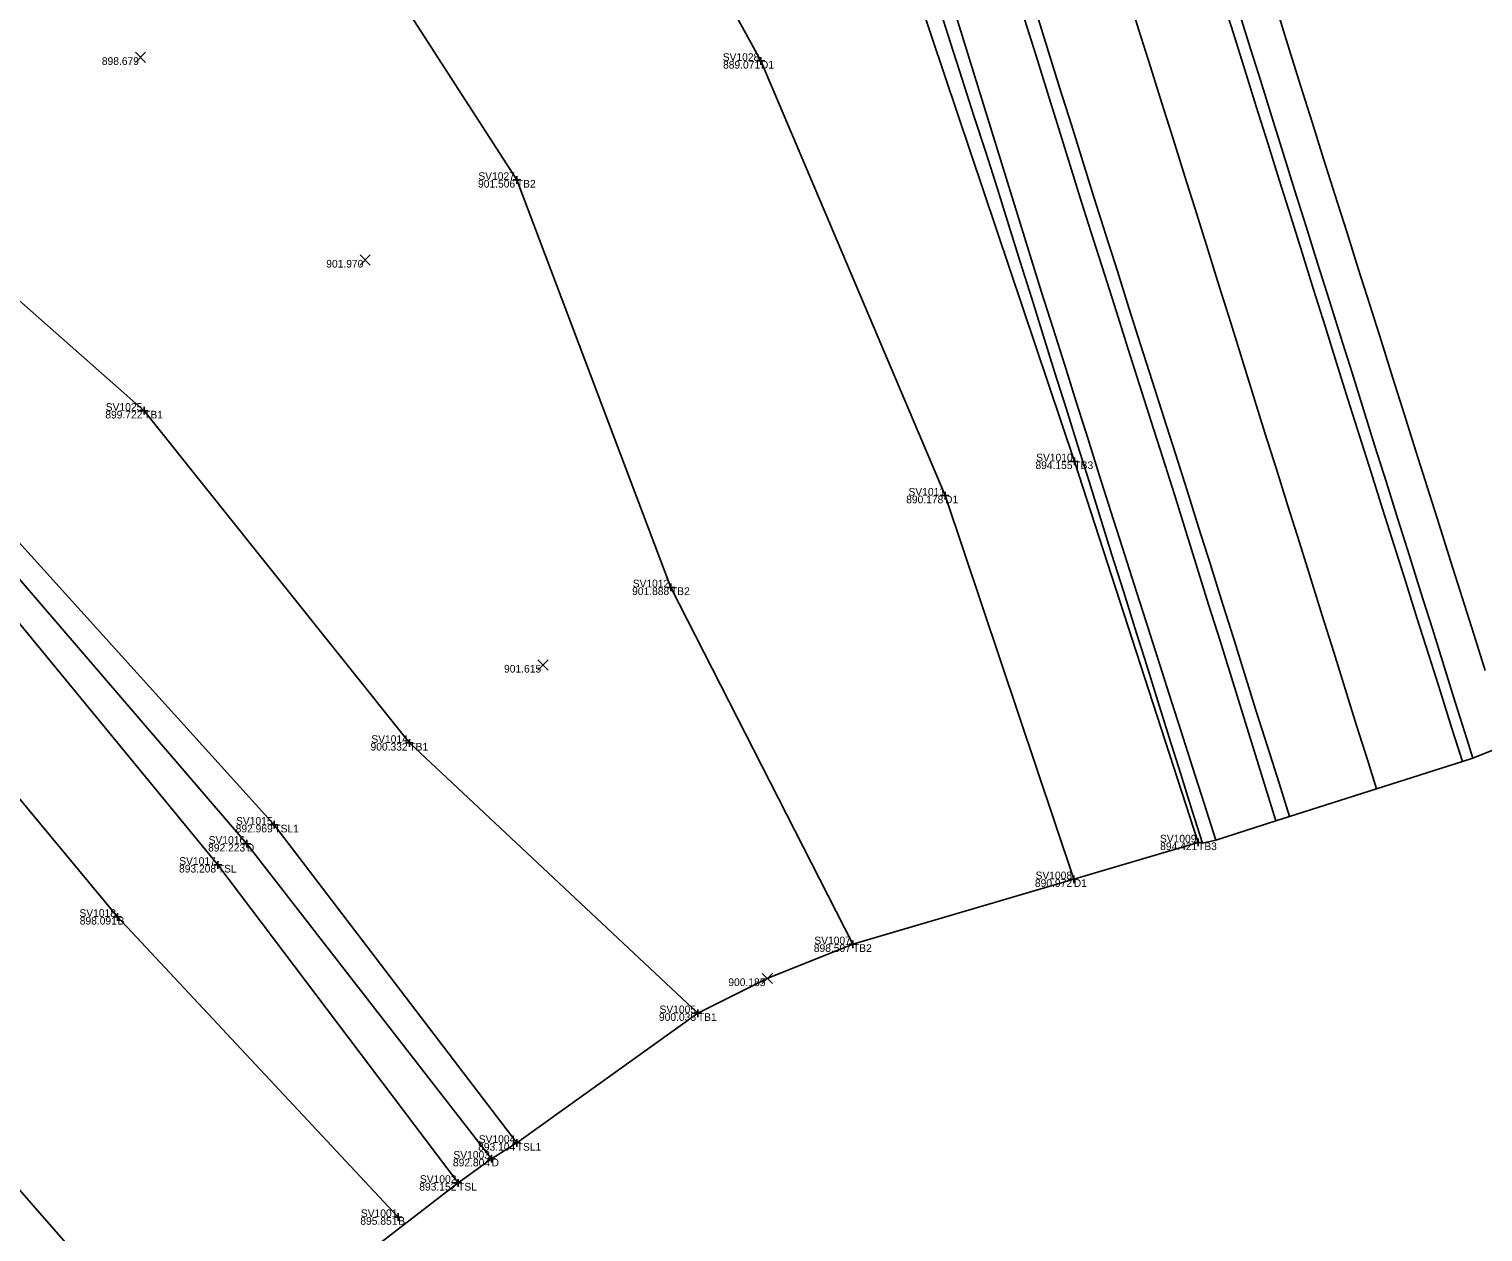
# Model space of a CAD drawing. Extents: x 1918148 to 1919797, y 624701 to 627089.
# Drawn here: x 1919158.7 to 1919348.2, y 625398.1 to 625555 of the extents above; entities that cross this region are included whole.
import ezdxf

# ---------------------------------------------------------------- set-up
doc = ezdxf.new("R2010")
doc.units = 0
for name, color, linetype in [('DR_X_Ditch', 7, 'Continuous'), ('DT_X_Terrain_Boundary', 7, 'Continuous'), ('PM_X_Edge_Line', 7, 'Continuous'), ('PM_X_Lane_Line', 7, 'Continuous'), ('PV_X_EOP', 7, 'Continuous'), ('PV_X_Shoulder_Aggregate', 7, 'Continuous'), ('PV_X_Shoulder_Rumble_Strip', 7, 'Continuous'), ('SV_X_Break_Lines', 7, 'Continuous'), ('SV_X_Random_Point', 7, 'Continuous'), ('SV_X_Shot_Marker', 7, 'Continuous'), ('SV_X_Text_Comment', 7, 'Continuous'), ('SV_X_Text_Elevation', 7, 'Continuous'), ('SV_X_Text_Name', 7, 'Continuous'), ('SV_X_Toe_of_Slope', 7, 'Continuous'), ('SV_X_Top_of_Bank', 7, 'Continuous')]:
    doc.layers.add(name, color=color, linetype=linetype)

msp = doc.modelspace()

# ---------------------------------------------------------------- linework, layer by layer
at = {"layer": 'DR_X_Ditch'}
for points in [[(1919294.9, 625444.11), (1919278.12, 625494.14), (1919254.13, 625550.83), (1919231.31, 625592.46), (1919223.61, 625606.59), (1919220.8, 625619.65), (1919215.15, 625628.65)], [(1919219.02, 625407.66), (1919187.13, 625448.73), (1919151.86, 625489.75), (1919129.02, 625518.23), (1919101.03, 625555.91), (1919077.07, 625591.12), (1919056.34, 625619.29)]]:
    msp.add_lwpolyline(points, dxfattribs=at)
at = {"layer": 'DT_X_Terrain_Boundary'}
for points in [[(1919348.54, 625471.32), (1919347.03, 625476.08), (1919345.53, 625480.85), (1919344.02, 625485.62), (1919342.52, 625490.39), (1919341.01, 625495.16), (1919339.5, 625499.92), (1919338, 625504.69), (1919336.49, 625509.46), (1919334.99, 625514.23), (1919333.49, 625519), (1919331.98, 625523.77), (1919330.48, 625528.53), (1919328.97, 625533.3), (1919327.47, 625538.07), (1919325.97, 625542.84), (1919324.47, 625547.61), (1919322.98, 625552.38), (1919321.48, 625557.15)], [(1919180.03, 625377.77), (1919214.66, 625404.51), (1919219.02, 625407.66), (1919222.3, 625409.72), (1919245.91, 625426.64), (1919254.95, 625431.18), (1919266.12, 625435.63), (1919294.9, 625444.11), (1919311.1, 625448.91), (1919311.66, 625448.82), (1919313.4, 625449.21), (1919321.24, 625451.71), (1919323.02, 625452.28), (1919334.37, 625455.9), (1919345.55, 625459.47), (1919346.92, 625459.9), (1919351.55, 625461.78)]]:
    msp.add_lwpolyline(points, dxfattribs=at)
at = {"layer": 'PM_X_Edge_Line'}
for points in [[(1919314.22, 625559.2), (1919315.71, 625554.42), (1919317.2, 625549.65), (1919318.69, 625544.88), (1919320.18, 625540.1), (1919321.67, 625535.33), (1919323.17, 625530.56), (1919324.66, 625525.79), (1919326.16, 625521.02), (1919327.65, 625516.25), (1919329.15, 625511.47), (1919330.64, 625506.7), (1919332.14, 625501.93), (1919333.64, 625497.16), (1919335.15, 625492.4), (1919336.65, 625487.63), (1919338.16, 625482.86), (1919339.67, 625478.09), (1919341.17, 625473.33), (1919342.68, 625468.56), (1919344.19, 625463.79), (1919345.55, 625459.47)], [(1919290.11, 625556.8), (1919291.6, 625552.02), (1919293.09, 625547.25), (1919294.59, 625542.48), (1919296.08, 625537.71), (1919297.57, 625532.93), (1919299.07, 625528.16), (1919300.58, 625523.4), (1919302.09, 625518.63), (1919303.61, 625513.87), (1919305.12, 625509.1), (1919306.63, 625504.34), (1919308.14, 625499.57), (1919309.66, 625494.8), (1919311.16, 625490.04), (1919312.66, 625485.27), (1919314.16, 625480.5), (1919315.66, 625475.73), (1919317.15, 625470.96), (1919318.65, 625466.18), (1919320.15, 625461.41), (1919321.65, 625456.64), (1919323.02, 625452.28)]]:
    msp.add_lwpolyline(points, dxfattribs=at)
at = {"layer": 'PM_X_Lane_Line'}
msp.add_lwpolyline([(1919301.89, 625559.61), (1919303.39, 625554.84), (1919304.88, 625550.07), (1919306.38, 625545.3), (1919307.88, 625540.53), (1919309.38, 625535.76), (1919310.88, 625530.99), (1919312.37, 625526.22), (1919313.86, 625521.44), (1919315.35, 625516.67), (1919316.84, 625511.9), (1919318.33, 625507.13), (1919319.82, 625502.35), (1919321.31, 625497.58), (1919322.81, 625492.81), (1919324.3, 625488.04), (1919325.8, 625483.27), (1919327.29, 625478.5), (1919328.78, 625473.72), (1919330.28, 625468.95), (1919331.77, 625464.18), (1919333.27, 625459.41), (1919334.37, 625455.9)], dxfattribs=at)
at = {"layer": 'PV_X_EOP'}
for points in [[(1919313.4, 625449.21), (1919311.88, 625453.97), (1919310.36, 625458.74), (1919308.84, 625463.5), (1919307.32, 625468.26), (1919305.8, 625473.03), (1919304.28, 625477.79), (1919302.76, 625482.55), (1919301.24, 625487.32), (1919299.73, 625492.08), (1919298.23, 625496.85), (1919296.73, 625501.62), (1919295.22, 625506.39), (1919293.72, 625511.16), (1919292.22, 625515.93), (1919290.71, 625520.69), (1919289.21, 625525.46), (1919287.73, 625530.24), (1919286.26, 625535.02), (1919284.78, 625539.8), (1919283.31, 625544.57), (1919281.84, 625549.35), (1919280.37, 625554.13), (1919278.9, 625558.91)], [(1919321.48, 625557.15), (1919322.98, 625552.38), (1919324.47, 625547.61), (1919325.97, 625542.84), (1919327.47, 625538.07), (1919328.97, 625533.3), (1919330.48, 625528.53), (1919331.98, 625523.77), (1919333.49, 625519), (1919334.99, 625514.23), (1919336.49, 625509.46), (1919338, 625504.69), (1919339.5, 625499.92), (1919341.01, 625495.16), (1919342.52, 625490.39), (1919344.02, 625485.62), (1919345.53, 625480.85), (1919347.03, 625476.08), (1919348.54, 625471.32)]]:
    msp.add_lwpolyline(points, dxfattribs=at)
at = {"layer": 'PV_X_Shoulder_Aggregate'}
msp.add_lwpolyline([(1919277.3, 625557.96), (1919278.83, 625553.2), (1919280.36, 625548.44), (1919281.89, 625543.68), (1919283.42, 625538.92), (1919284.94, 625534.15), (1919286.44, 625529.38), (1919287.93, 625524.61), (1919289.43, 625519.84), (1919290.92, 625515.07), (1919292.41, 625510.3), (1919293.91, 625505.53), (1919295.4, 625500.75), (1919296.9, 625495.98), (1919298.39, 625491.21), (1919299.88, 625486.44), (1919301.38, 625481.67), (1919302.87, 625476.9), (1919304.37, 625472.12), (1919305.86, 625467.35), (1919307.35, 625462.58), (1919308.85, 625457.81), (1919310.34, 625453.04), (1919311.66, 625448.82)], dxfattribs=at)
at = {"layer": 'PV_X_Shoulder_Rumble_Strip'}
for points in [[(1919316.25, 625557.87), (1919317.73, 625553.1), (1919319.22, 625548.32), (1919320.71, 625543.55), (1919322.2, 625538.78), (1919323.69, 625534.01), (1919325.19, 625529.24), (1919326.68, 625524.46), (1919328.18, 625519.69), (1919329.67, 625514.92), (1919331.17, 625510.15), (1919332.66, 625505.38), (1919334.16, 625500.61), (1919335.65, 625495.84), (1919337.15, 625491.07), (1919338.65, 625486.29), (1919340.14, 625481.52), (1919341.64, 625476.75), (1919343.13, 625471.98), (1919344.63, 625467.21), (1919346.12, 625462.44), (1919346.92, 625459.9)], [(1919288.49, 625556.28), (1919289.98, 625551.51), (1919291.47, 625546.73), (1919292.95, 625541.96), (1919294.44, 625537.19), (1919295.93, 625532.41), (1919297.43, 625527.64), (1919298.94, 625522.88), (1919300.45, 625518.11), (1919301.96, 625513.35), (1919303.47, 625508.58), (1919304.99, 625503.81), (1919306.5, 625499.05), (1919308.01, 625494.28), (1919309.51, 625489.51), (1919311, 625484.74), (1919312.48, 625479.96), (1919313.96, 625475.19), (1919315.44, 625470.41), (1919316.92, 625465.64), (1919318.41, 625460.86), (1919319.89, 625456.09), (1919321.24, 625451.71)]]:
    msp.add_lwpolyline(points, dxfattribs=at)
at = {"layer": 'SV_X_Break_Lines'}
msp.add_lwpolyline([(1919206.86, 625400.05), (1919170.29, 625439.2), (1919138.05, 625478.01), (1919112.93, 625508.78), (1919087.56, 625546), (1919063.33, 625584.96), (1919048.27, 625604.54), (1919031.79, 625617.49), (1919020.42, 625620.88), (1919013.82, 625627.54), (1919010.2, 625639.42), (1919006.75, 625653.62), (1919000.26, 625672.97)], dxfattribs=at)
at = {"layer": 'SV_X_Random_Point'}
for p, q in [((1919172.6, 625550.64), (1919173.93, 625551.97)), ((1919172.6, 625551.97), (1919173.93, 625550.64)), ((1919201.88, 625524.21), (1919203.21, 625525.55)), ((1919201.88, 625525.55), (1919203.21, 625524.21)), ((1919225.06, 625471.39), (1919226.39, 625472.73)), ((1919225.06, 625472.73), (1919226.39, 625471.39)), ((1919254.29, 625430.51), (1919255.62, 625431.84)), ((1919254.29, 625431.84), (1919255.62, 625430.51))]:
    msp.add_line(p, q, dxfattribs=at)
at = {"layer": 'SV_X_Shot_Marker'}
for p, q in [((1919253.63, 625550.83), (1919254.63, 625550.83)), ((1919254.13, 625551.33), (1919254.13, 625550.33)), ((1919254.13, 625550.83), (1919254.13, 625550.83)), ((1919221.82, 625535.31), (1919222.82, 625535.31)), ((1919222.32, 625535.81), (1919222.32, 625534.81)), ((1919222.32, 625535.31), (1919222.32, 625535.31)), ((1919173.24, 625505.2), (1919174.24, 625505.2)), ((1919173.74, 625505.7), (1919173.74, 625504.7)), ((1919173.74, 625505.2), (1919173.74, 625505.2)), ((1919294.98, 625499.11), (1919294.98, 625498.11)), ((1919294.48, 625498.61), (1919295.48, 625498.61)), ((1919294.98, 625498.61), (1919294.98, 625498.61)), ((1919277.62, 625494.14), (1919278.62, 625494.14)), ((1919278.12, 625494.64), (1919278.12, 625493.64)), ((1919278.12, 625494.14), (1919278.12, 625494.14)), ((1919241.9, 625482.18), (1919242.9, 625482.18)), ((1919242.4, 625482.68), (1919242.4, 625481.68)), ((1919242.4, 625482.18), (1919242.4, 625482.18)), ((1919207.81, 625461.89), (1919208.81, 625461.89)), ((1919208.31, 625462.39), (1919208.31, 625461.39)), ((1919208.31, 625461.89), (1919208.31, 625461.89)), ((1919190.71, 625451.72), (1919190.71, 625450.72)), ((1919190.21, 625451.22), (1919191.21, 625451.22)), ((1919190.71, 625451.22), (1919190.71, 625451.22)), ((1919186.63, 625448.73), (1919187.63, 625448.73)), ((1919187.13, 625449.23), (1919187.13, 625448.23)), ((1919187.13, 625448.73), (1919187.13, 625448.73)), ((1919310.6, 625448.91), (1919311.6, 625448.91)), ((1919311.1, 625449.41), (1919311.1, 625448.41)), ((1919311.1, 625448.91), (1919311.1, 625448.91)), ((1919182.85, 625445.99), (1919183.85, 625445.99)), ((1919183.35, 625446.49), (1919183.35, 625445.49)), ((1919183.35, 625445.99), (1919183.35, 625445.99)), ((1919294.4, 625444.11), (1919295.4, 625444.11)), ((1919294.9, 625444.61), (1919294.9, 625443.61)), ((1919294.9, 625444.11), (1919294.9, 625444.11)), ((1919169.79, 625439.2), (1919170.79, 625439.2)), ((1919170.29, 625439.7), (1919170.29, 625438.7)), ((1919170.29, 625439.2), (1919170.29, 625439.2)), ((1919265.62, 625435.63), (1919266.62, 625435.63)), ((1919266.12, 625436.13), (1919266.12, 625435.13)), ((1919266.12, 625435.63), (1919266.12, 625435.63)), ((1919245.91, 625427.14), (1919245.91, 625426.14)), ((1919245.41, 625426.64), (1919246.41, 625426.64)), ((1919245.91, 625426.64), (1919245.91, 625426.64)), ((1919222.3, 625410.22), (1919222.3, 625409.22)), ((1919219.02, 625408.16), (1919219.02, 625407.16)), ((1919221.8, 625409.72), (1919222.8, 625409.72)), ((1919222.3, 625409.72), (1919222.3, 625409.72)), ((1919218.52, 625407.66), (1919219.52, 625407.66)), ((1919219.02, 625407.66), (1919219.02, 625407.66)), ((1919214.16, 625404.51), (1919215.16, 625404.51)), ((1919214.66, 625405.01), (1919214.66, 625404.01)), ((1919214.66, 625404.51), (1919214.66, 625404.51)), ((1919206.86, 625400.55), (1919206.86, 625399.55)), ((1919206.36, 625400.05), (1919207.36, 625400.05)), ((1919206.86, 625400.05), (1919206.86, 625400.05))]:
    msp.add_line(p, q, dxfattribs=at)
at = {"layer": 'SV_X_Toe_of_Slope'}
for points in [[(1919222.3, 625409.72), (1919190.71, 625451.22), (1919154.52, 625491.26), (1919132.35, 625520.35), (1919103.41, 625557.58), (1919078.28, 625592.14), (1919056.75, 625620.59)], [(1919214.66, 625404.51), (1919183.35, 625445.99), (1919149.18, 625487.49), (1919126.62, 625516.79), (1919098.28, 625553.96), (1919075.71, 625589.98), (1919054.68, 625616.82)]]:
    msp.add_lwpolyline(points, dxfattribs=at)
at = {"layer": 'SV_X_Top_of_Bank'}
for points in [[(1919180.03, 625377.77), (1919142.39, 625420.85), (1919113.9, 625458.17), (1919086.6, 625489.42), (1919057.39, 625523.08), (1919019.76, 625570.22), (1918998.07, 625602.27), (1918985.26, 625627.56), (1918968.39, 625668.03), (1918955.62, 625707.63), (1918947.9, 625739.17), (1918945.04, 625765.59), (1918947.37, 625785.94), (1918957.93, 625802.75), (1918975.61, 625809.21), (1918997.58, 625813.39), (1919030.67, 625814.44), (1919065.45, 625812.35), (1919111.29, 625808.54)], [(1919311.1, 625448.91), (1919294.98, 625498.61), (1919274.7, 625559.01), (1919260.24, 625603.73), (1919254.49, 625621.03), (1919244.11, 625659.16), (1919235.03, 625683.79), (1919222.11, 625721.27), (1919200.65, 625791.17)], [(1919245.91, 625426.64), (1919208.31, 625461.89), (1919173.74, 625505.2), (1919145.85, 625529.79), (1919119.2, 625567.31), (1919087.64, 625598.97), (1919076.93, 625609.87), (1919071.18, 625616.65)], [(1919266.12, 625435.63), (1919242.4, 625482.18), (1919222.32, 625535.31), (1919199.99, 625569.95), (1919193.11, 625584.33), (1919176.48, 625601.38)]]:
    msp.add_lwpolyline(points, dxfattribs=at)

# ---------------------------------------------------------------- texts
at = {"layer": 'SV_X_Text_Comment'}
for s, p in [('D1', (1919254.13, 625549.83)), ('TB2', (1919222.32, 625534.31)), ('TB1', (1919173.74, 625504.2)), ('TB3', (1919294.98, 625497.61)), ('D1', (1919278.12, 625493.14)), ('TB2', (1919242.4, 625481.18)), ('TB1', (1919208.31, 625460.89)), ('TSL1', (1919190.71, 625450.22)), ('D', (1919187.13, 625447.73)), ('TB3', (1919311.1, 625447.91)), ('TSL', (1919183.35, 625444.99)), ('D1', (1919294.9, 625443.11)), ('B', (1919170.29, 625438.2)), ('TB2', (1919266.12, 625434.63)), ('TB1', (1919245.91, 625425.64)), ('TSL1', (1919222.3, 625408.72)), ('D', (1919219.02, 625406.66)), ('TSL', (1919214.66, 625403.51)), ('B', (1919206.86, 625399.05))]:
    msp.add_text(s, height=1, dxfattribs=at).set_placement(p)
at = {"layer": 'SV_X_Text_Elevation'}
for s, p in [('898.679', (1919168.23, 625550.31)), ('889.071', (1919249.19, 625549.83)), ('901.506', (1919217.26, 625534.31)), ('901.970', (1919197.48, 625523.88)), ('899.722', (1919168.68, 625504.2)), ('894.155', (1919289.91, 625497.61)), ('890.178', (1919273.06, 625493.14)), ('901.888', (1919237.34, 625481.18)), ('901.615', (1919220.65, 625471.06)), ('900.332', (1919203.25, 625460.89)), ('892.969', (1919185.67, 625450.22)), ('892.223', (1919182.08, 625447.73)), ('894.421', (1919306.16, 625447.91)), ('893.208', (1919178.29, 625444.99)), ('890.972', (1919289.84, 625443.11)), ('898.091', (1919165.35, 625438.2)), ('898.507', (1919261.02, 625434.63)), ('900.185', (1919249.88, 625430.18)), ('900.035', (1919240.84, 625425.64)), ('893.104', (1919217.27, 625408.72)), ('892.804', (1919213.99, 625406.66)), ('893.152', (1919209.6, 625403.51)), ('895.851', (1919201.92, 625399.05))]:
    msp.add_text(s, height=1, dxfattribs=at).set_placement(p)
at = {"layer": 'SV_X_Text_Name'}
for s, p in [('SV1028', (1919249.15, 625550.83)), ('SV1027', (1919217.3, 625535.31)), ('SV1025', (1919168.74, 625505.2)), ('SV1010', (1919290, 625498.61)), ('SV1011', (1919273.36, 625494.14)), ('SV1012', (1919237.42, 625482.18)), ('SV1014', (1919203.35, 625461.89)), ('SV1015', (1919185.72, 625451.22)), ('SV1016', (1919182.15, 625448.73)), ('SV1009', (1919306.13, 625448.91)), ('SV1017', (1919178.32, 625445.99)), ('SV1008', (1919289.92, 625444.11)), ('SV1018', (1919165.31, 625439.2)), ('SV1007', (1919261.09, 625435.63)), ('SV1005', (1919240.91, 625426.64)), ('SV1004', (1919217.35, 625409.72)), ('SV1003', (1919214.05, 625407.66)), ('SV1002', (1919209.68, 625404.51)), ('SV1001', (1919201.99, 625400.05))]:
    msp.add_text(s, height=1, dxfattribs=at).set_placement(p)

doc.saveas('drawing.dxf')
